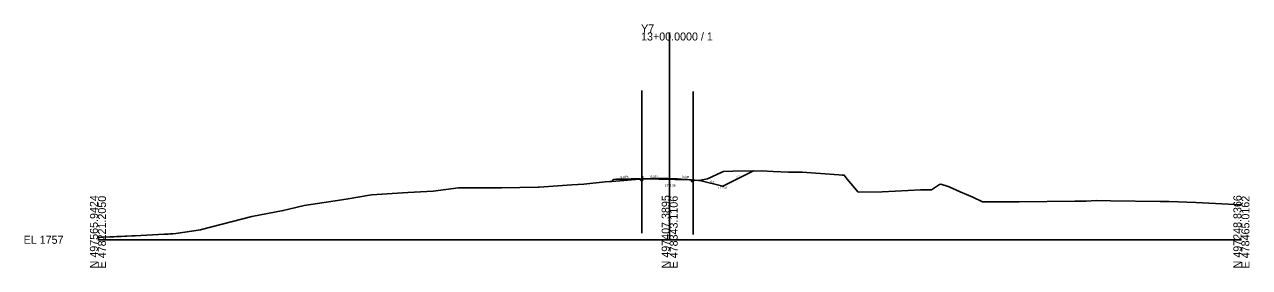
# Model space of a CAD drawing. Extents: x -26 to 403, y -10 to 4071.
# Drawn here: x -25.7 to 402.8, y 2990.3 to 3075.3 of the extents above; entities that cross this region are included whole.
import ezdxf

# ---------------------------------------------------------------- set-up
doc = ezdxf.new("R2010")
doc.units = 0
for name, color, linetype in [('Exist Cross Section Cell', 7, 'Continuous'), ('Exist XS Center Line Elevation Label', 7, 'Continuous'), ('Exist XS Ground Line', 7, 'Continuous'), ('Prop Road Sect_ Boring - Header (ID Tx)', 7, 'Continuous'), ('Prop XS Ditch Slope Text', 7, 'Continuous'), ('Prop XS Ditch Standard Text', 7, 'Continuous'), ('Prop XS Dump Level', 7, 'Continuous'), ('Prop XS Earthwork Shape', 7, 'Continuous'), ('Prop XS EOT Tick Mark', 7, 'Continuous'), ('Prop XS Finish Grade', 7, 'Continuous'), ('Prop XS Finish Grade Earthwork', 7, 'Continuous'), ('Prop XS Finish Grade Pavement', 7, 'Continuous'), ('Prop XS Pvmt Edge Slope', 7, 'Continuous'), ('Prop XS SE Text', 7, 'Continuous'), ('Prop XS Side Slope Text', 7, 'Continuous'), ('Prop XS Subgrade Earthwork', 7, 'Continuous'), ('Scratch_Level_2', 7, 'Continuous'), ('Scratch_Level_6', 7, 'Continuous')]:
    doc.layers.add(name, color=color, linetype=linetype)

msp = doc.modelspace()

# ---------------------------------------------------------------- linework, layer by layer
at = {"layer": 'Exist Cross Section Cell'}
for p, q in [((200, 3000), (200, 3072.53)), ((0, 3000), (200, 3000)), ((200, 3000), (400, 3000))]:
    msp.add_line(p, q, dxfattribs=at)
at = {"layer": 'Exist XS Ground Line'}
msp.add_lwpolyline([(0, 3000.79), (1.42, 3000.87), (4.13, 3000.98), (5.52, 3001.04), (6.57, 3001.11), (7.34, 3001.14), (8.17, 3001.18), (9.46, 3001.22), (10.05, 3001.25), (11.9, 3001.37), (12.97, 3001.41), (15.04, 3001.51), (21.19, 3001.83), (23.31, 3001.94), (24.55, 3002), (25.28, 3002.04), (26.24, 3002.1), (27.19, 3002.16), (35.82, 3003.5), (36.26, 3003.6), (53.84, 3008.13), (64.82, 3010.25), (66.83, 3010.73), (72.15, 3011.96), (79.17, 3013), (86.79, 3014.16), (95.73, 3015.69), (108.4, 3016.55), (117.32, 3017.06), (126.1, 3018.18), (134.72, 3018.2), (140.8, 3018.2), (141.18, 3018.21), (153.99, 3018.41), (154.39, 3018.43), (162.47, 3018.97), (165.77, 3019.21), (169.95, 3019.44), (177.4, 3020.25), (179.11, 3020.39), (179.82, 3020.44), (180.32, 3021.04), (181.4, 3021.22), (181.81, 3021.25), (183.33, 3021.23), (183.89, 3021.24), (186.49, 3021.31), (189.01, 3021.29), (189.71, 3021.28), (190.18, 3021.27), (190.56, 3021.29), (190.93, 3021.31), (193.37, 3021.41), (194.24, 3021.41), (195.52, 3021.39), (196.51, 3021.39), (197.31, 3021.39), (198.33, 3021.39), (199.4, 3021.39), (199.98, 3021.38), (202.78, 3021.31), (204.07, 3021.24), (205.93, 3021.14), (206.29, 3021.11), (207.65, 3020.92), (208.34, 3020.87), (210.1, 3020.71), (212.68, 3021.27), (213.2, 3021.37), (218.23, 3023.61), (218.83, 3023.91), (222.11, 3024.02), (232.1, 3024.18), (236.25, 3023.92), (241.53, 3023.64), (246.37, 3023.68), (259.15, 3022.7), (260.29, 3022.64), (261.08, 3022.56), (262.06, 3021.26), (265.96, 3016.67), (274.31, 3016.78), (283.41, 3017.2), (287.76, 3017.46), (291.64, 3017.5), (294.36, 3019.34), (294.89, 3019.49), (297.4, 3018.61), (297.74, 3018.48), (301.67, 3016.78), (306.08, 3014.9), (309.4, 3013.31), (317.3, 3013.28), (322.22, 3013.29), (341.77, 3013.49), (345.37, 3013.54), (345.7, 3013.55), (349.16, 3013.77), (354.16, 3013.68), (371.59, 3013.43), (374.68, 3013.39), (384.04, 3013.08), (400, 3012.22)], dxfattribs=at)
at = {"layer": 'Prop Road Sect_ Boring - Header (ID Tx)'}
for points in [[(190.55, 3021.29), (189.44, 3021.21), (189.95, 3020.7)], [(190.55, 3021.29), (189.44, 3021.21), (189.95, 3020.7), (190.55, 3020.71)], [(190.55, 3020.71), (189.95, 3020.7), (190.55, 3021.29)], [(207.59, 3021.01), (208.73, 3020.92), (208.21, 3020.4)]]:
    msp.add_lwpolyline(points, close=True, dxfattribs=at)
at = {"layer": 'Prop XS Dump Level'}
for p, q in [((190.55, 3021.29), (200, 3021.36)), ((200, 3021.38), (207.59, 3021.01))]:
    msp.add_line(p, q, dxfattribs=at)
at = {"layer": 'Prop XS Earthwork Shape'}
for points in [[(190.55, 3020.71), (190.55, 3021.29), (190.18, 3021.27), (189.71, 3021.28), (189.01, 3021.29), (186.49, 3021.31), (183.89, 3021.24), (183.33, 3021.23), (181.81, 3021.25), (181.4, 3021.22), (180.32, 3021.04), (179.82, 3020.44), (189.44, 3021.21), (189.95, 3020.7)], [(218.23, 3023.61), (218.83, 3023.91), (222.11, 3024.02), (229.31, 3024.13), (218.59, 3018.77), (210.59, 3020.77), (210.45, 3020.79), (212.68, 3021.27), (213.2, 3021.37)], [(208.34, 3020.87), (208.65, 3020.84), (208.21, 3020.4), (207.59, 3020.43), (207.59, 3020.93), (207.65, 3020.92)], [(208.65, 3020.84), (210.1, 3020.71), (210.45, 3020.79), (208.73, 3020.92)]]:
    msp.add_lwpolyline(points, close=True, dxfattribs=at)
at = {"layer": 'Prop XS EOT Tick Mark'}
msp.add_line((190.55, 3021.29), (190.55, 3022.29), dxfattribs=at)
at = {"layer": 'Prop XS Finish Grade'}
for p, q in [((190.55, 3021.29), (189.44, 3021.21)), ((207.59, 3021.01), (208.73, 3020.92))]:
    msp.add_line(p, q, dxfattribs=at)
at = {"layer": 'Prop XS Finish Grade Earthwork'}
for p, q in [((189.44, 3021.21), (179.82, 3020.44)), ((218.59, 3018.77), (229.31, 3024.13)), ((208.73, 3020.92), (210.59, 3020.77)), ((210.59, 3020.77), (218.59, 3018.77))]:
    msp.add_line(p, q, dxfattribs=at)
at = {"layer": 'Prop XS Finish Grade Pavement'}
for p, q in [((190.55, 3021.29), (200, 3021.36)), ((200, 3021.38), (207.59, 3021.01))]:
    msp.add_line(p, q, dxfattribs=at)
at = {"layer": 'Prop XS Pvmt Edge Slope'}
for p, q in [((190.55, 3021.29), (189.95, 3020.7)), ((207.59, 3021.01), (208.21, 3020.4))]:
    msp.add_line(p, q, dxfattribs=at)
at = {"layer": 'Prop XS Subgrade Earthwork'}
for p, q in [((189.95, 3020.7), (189.44, 3021.21)), ((190.55, 3020.71), (190.55, 3021.29)), ((190.55, 3020.71), (189.95, 3020.7)), ((207.59, 3020.43), (207.59, 3020.93)), ((207.59, 3020.43), (208.21, 3020.4)), ((208.21, 3020.4), (208.73, 3020.92))]:
    msp.add_line(p, q, dxfattribs=at)
at = {"layer": 'Scratch_Level_2'}
for p, q in [((190.24, 3052.28), (190.24, 3002.28)), ((208.27, 3051.87), (208.27, 3001.87))]:
    msp.add_line(p, q, dxfattribs=at)
at = {"layer": 'Scratch_Level_6'}
msp.add_line((190.55, 3021.29), (207.59, 3020.93), dxfattribs=at)

# ---------------------------------------------------------------- texts
at = {"layer": 'Exist Cross Section Cell'}
for s, p in [('Y7', (190, 3072.53)), ('13+00.0000 / 1', (190, 3069.73)), ('EL 1757', (-26, 2998.6))]:
    msp.add_text(s, height=2.8, dxfattribs=at).set_placement(p)
for s, p in [('N 497565.9424', (0, 2990)), ('E 478221.2050', (2.8, 2990)), ('N 497407.3895', (200, 2990)), ('E 478343.1106', (202.8, 2990)), ('N 497248.8366', (400, 2990)), ('E 478465.0162', (402.8, 2990))]:
    msp.add_text(s, height=2.8, rotation=90, dxfattribs=at).set_placement(p)
at = {"layer": 'Exist XS Center Line Elevation Label'}
msp.add_text('1778.38', height=0.75, dxfattribs=at).set_placement((198.27, 3018.63))
at = {"layer": 'Prop XS Ditch Slope Text'}
msp.add_text('4:1', height=0.75, rotation=345.9638, dxfattribs=at).set_placement((214.05, 3020.11))
at = {"layer": 'Prop XS Ditch Standard Text'}
msp.add_text('1775.61', height=0.75, dxfattribs=at).set_placement((216.93, 3017.86))
at = {"layer": 'Prop XS Dump Level'}
msp.add_text('Case1', height=0.04, rotation=359.7513, dxfattribs=at).set_placement((187.55, 3021.04))
msp.add_text('Case1', height=0.04, dxfattribs=at).set_placement((210.59, 3020.73))
at = {"layer": 'Prop XS SE Text'}
for s, rotation, p in [('0.012', 0.6684, (193.32, 3021.8)), ('0.048', 357.2329, (204.22, 3021.68))]:
    msp.add_text(s, height=0.75, rotation=rotation, dxfattribs=at).set_placement(p)
at = {"layer": 'Prop XS Side Slope Text'}
for s, rotation, p in [('8.03%', 4.59, (182.82, 3021.53)), ('2:1', 26.5651, (223.48, 3021.42))]:
    msp.add_text(s, height=0.75, rotation=rotation, dxfattribs=at).set_placement(p)

doc.saveas('drawing.dxf')
